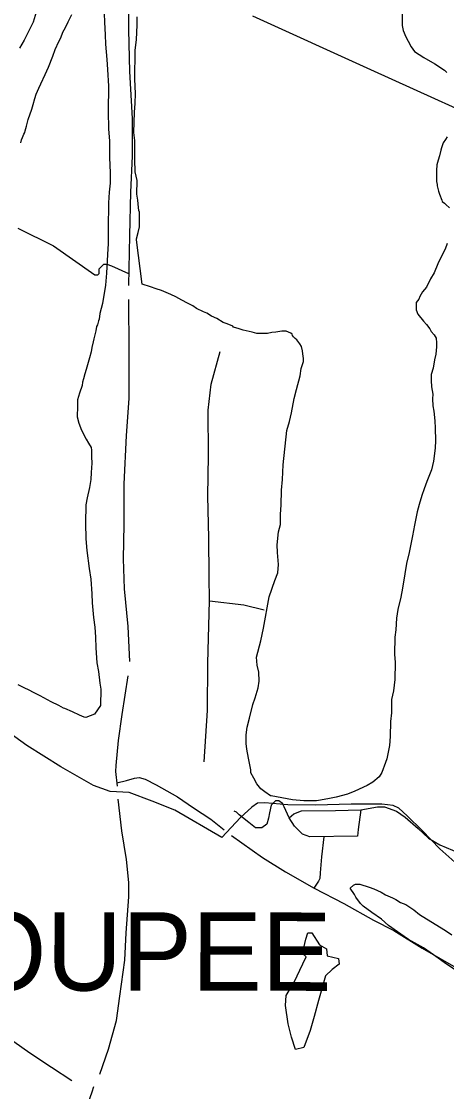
# Model space of a CAD drawing. Extents: x 3263578 to 3301413, y 764927 to 798602.
# Drawn here: x 3272360 to 3273446, y 781990 to 784722 of the extents above; entities that cross this region are included whole.
import ezdxf

# ---------------------------------------------------------------- set-up
doc = ezdxf.new("R2010")
doc.units = 0
for name, color, linetype in [('V-ROAD-CNTR', 7, 'Continuous'), ('V-SITE-VEGE', 7, 'Continuous'), ('V-TOPO-GNAM-IDEN', 7, 'Continuous'), ('V-TOPO-SHOR', 7, 'Continuous')]:
    doc.layers.add(name, color=color, linetype=linetype)

msp = doc.modelspace()

# ---------------------------------------------------------------- linework, layer by layer
at = {"layer": 'V-ROAD-CNTR'}
for points in [[(3272871.3, 782638.4), (3272751.2, 782707.9), (3272693.7, 782731), (3272634.6, 782753.7), (3272586.4, 782755.6), (3272544.2, 782771.2), (3272460.4, 782818.6), (3272374.1, 782873), (3272302.5, 782924.3)], [(3273887.3, 782394.1), (3273845.6, 782422.1), (3273790.5, 782448.5), (3273704.1, 782475), (3273634.8, 782502), (3273573.5, 782523.4), (3273524.5, 782537.4), (3273481.9, 782562.3), (3273428.5, 782609.9), (3273383.6, 782656.6), (3273344.9, 782694.2), (3273323.2, 782713.3), (3273309.1, 782720.4), (3273280.1, 782723.2), (3273202.1, 782723.7), (3273111.2, 782721.1), (3273040.2, 782722.2), (3272981.6, 782727.4), (3272962.7, 782725.9), (3272948.4, 782716.1), (3272919.2, 782689.5), (3272871.3, 782638.4)]]:
    msp.add_lwpolyline(points, dxfattribs=at)
at = {"layer": 'V-SITE-VEGE'}
for points in [[(3272566.9, 784897.4), (3272566.8, 784890.8), (3272565.5, 784879.7), (3272566.3, 784859.7), (3272566.1, 784844.1), (3272568.2, 784837.4), (3272567.5, 784796.3), (3272568.1, 784766.3), (3272571.1, 784742.9), (3272571.9, 784720.7), (3272573.6, 784688.4), (3272574.3, 784664)], [(3272397.8, 784745.7), (3272389.6, 784720.3), (3272381.6, 784703.7), (3272366.7, 784674), (3272355.2, 784654.1)], [(3272358, 784411.9), (3272360.4, 784419.6), (3272362.7, 784426.2), (3272366.1, 784434), (3272368.4, 784438.4), (3272369.6, 784442.8), (3272373.1, 784455), (3272376.7, 784471.6), (3272386.1, 784498.1), (3272389.6, 784510.3), (3272394.3, 784525.7), (3272397.8, 784536.8), (3272404.7, 784552.2), (3272409.3, 784563.3), (3272420.8, 784586.4), (3272428.9, 784605.2), (3272440.5, 784633.9), (3272446.3, 784650.5), (3272455.5, 784671.4), (3272460.1, 784680.2), (3272465.9, 784694.6), (3272472.7, 784706.7), (3272479.6, 784721), (3272488.8, 784739.8)], [(3272945.7, 782811.3), (3272942.6, 782828), (3272939.5, 782841.4), (3272935.4, 782863.7), (3272933.4, 782878.1), (3272933.8, 782900.3), (3272936.3, 782920.3), (3272942.2, 782943.5), (3272950.6, 782977.9), (3272956.4, 782995.5), (3272964.6, 783021), (3272967.1, 783037.6), (3272966.3, 783060.9), (3272962.2, 783078.8), (3272960.3, 783098.8), (3272971, 783140.9), (3272978.1, 783173), (3272992.8, 783252.8), (3273006.8, 783294.7), (3273014.9, 783314.6), (3273016.3, 783335.7), (3273013.5, 783365.8), (3273012.7, 783385.8), (3273016.5, 783419), (3273021.3, 783437.9), (3273021.7, 783464.5), (3273023.2, 783486.7), (3273023.8, 783525.6), (3273026.5, 783552.2), (3273028.2, 783590), (3273037.4, 783677.6), (3273044.4, 783700.8), (3273049.2, 783723), (3273056.4, 783759.5), (3273062.4, 783782.8), (3273071.8, 783817.1), (3273074.3, 783835.9), (3273080.2, 783853.6), (3273080.3, 783861.4), (3273078.3, 783873.6), (3273077.3, 783881.4), (3273075.2, 783892.6), (3273070.9, 783899.3), (3273063.3, 783909.4), (3273058.9, 783912.8), (3273054.5, 783917.3), (3273052.4, 783920.7), (3273051.3, 783924.1), (3273048, 783926.3), (3273035.9, 783931), (3273024.8, 783931.2), (3273009.2, 783929.2), (3272999.2, 783928.2), (3272988, 783925.1), (3272961.3, 783925.5), (3272949.2, 783929), (3272925.9, 783933.8), (3272916, 783937.3), (3272901.6, 783942), (3272899.4, 783944.3), (3272885.1, 783950.1), (3272875.1, 783953.6), (3272858.6, 783963.8), (3272845.4, 783969.6), (3272833.3, 783977.6), (3272824.4, 783981), (3272806.8, 783989.1), (3272798, 783995.9), (3272783.7, 784002.8), (3272769.4, 784010.8), (3272753.9, 784018.8), (3272741.8, 784024.6), (3272717.5, 784035), (3272704.3, 784039.6), (3272689.9, 784044.3), (3272667.8, 784051.3), (3272654.1, 784164.9), (3272654.1, 784167.1), (3272657.7, 784183.7), (3272661.3, 784198.1), (3272661.8, 784234.8), (3272659.7, 784239.2), (3272658.7, 784247), (3272656.8, 784266), (3272654.8, 784281.5), (3272655.4, 784316), (3272650.2, 784338.3), (3272649.6, 784369.4), (3272649.9, 784390.5), (3272649.2, 784418.3), (3272647.3, 784438.3), (3272648.2, 784490.5), (3272650.7, 784512.7), (3272651.2, 784538.3), (3272649.5, 784575), (3272650.7, 784648.3), (3272653.4, 784676), (3272655.1, 784712.7), (3272655.4, 784733.8)], [(3273332.3, 784745.1), (3273331.7, 784711.8), (3273334.9, 784699.5), (3273341.3, 784682.8), (3273347.8, 784671.5), (3273355.3, 784657), (3273364, 784645.7), (3273387.1, 784629.8), (3273415.7, 784613.8), (3273439.9, 784597.8), (3273446.5, 784592.2)], [(3272574.3, 784664), (3272578.1, 784625), (3272579.9, 784599.4), (3272582.6, 784557.2), (3272581.5, 784492.7), (3272581.9, 784447.2), (3272584.8, 784417.1), (3272585.2, 784374.9), (3272586.8, 784336), (3272586.4, 784309.3), (3272583.8, 784286), (3272582.2, 784259.4), (3272581.2, 784192.7), (3272581.7, 784154.9), (3272580.1, 784127.2), (3272577.1, 784079.5), (3272574.4, 784048.4), (3272567, 784001.8), (3272559.9, 783976.4), (3272558.6, 783962), (3272556.3, 783957.6), (3272553.9, 783947.6), (3272551.6, 783943.2), (3272550.3, 783932.1), (3272544.4, 783912.2), (3272543.2, 783904.4), (3272539.6, 783890), (3272538.3, 783879), (3272533.7, 783863.5), (3272530.1, 783851.3), (3272525.4, 783833.6), (3272521.9, 783822.6), (3272518.3, 783809.3), (3272516, 783801.5), (3272514.7, 783792.7), (3272507.8, 783772.8), (3272503, 783756.2), (3272502.8, 783739.5), (3272502.3, 783712.9), (3272506.5, 783696.1), (3272512.9, 783678.2), (3272524.8, 783655.8), (3272531.3, 783645.7), (3272537.8, 783634.5), (3272538.8, 783627.8), (3272538.5, 783610.1), (3272539.3, 783594.5), (3272537.8, 783570.1), (3272537.5, 783552.3), (3272533.9, 783532.3), (3272527.9, 783505.8), (3272524.3, 783488.1), (3272523.5, 783441.4), (3272524, 783401.4), (3272526.9, 783371.3), (3272532.8, 783325.7), (3272536.8, 783297.8), (3272539.5, 783261.1), (3272540.3, 783237.8), (3272544.1, 783200), (3272547.1, 783175.5), (3272548.9, 783149.9), (3272549.5, 783123.2), (3272552.3, 783084.3), (3272556.3, 783062), (3272560.3, 783033), (3272562.3, 783017.4), (3272561.6, 782975.2), (3272546.8, 782953.2), (3272524.5, 782944.7), (3272520, 782945.9), (3272507.9, 782950.5), (3272490.3, 782959.7), (3272470.4, 782967.8), (3272467.1, 782969), (3272455, 782975.8), (3272436.2, 782985), (3272407.6, 782999.9), (3272392.1, 783007.9), (3272377.8, 783015.9), (3272369, 783019.4), (3272351.4, 783028.6)], [(3273447.2, 784427.7), (3273442.6, 784421.1), (3273436.9, 784412.3), (3273432.3, 784399.1), (3273431.1, 784393.5), (3273427.5, 784379.1), (3273424, 784368.1), (3273420.5, 784355.9), (3273420.2, 784341.5), (3273419.8, 784313.7), (3273421.9, 784305.9), (3273421.8, 784302.6), (3273422.8, 784295.9), (3273425, 784289.2), (3273427.1, 784281.4), (3273433.5, 784265.7), (3273434.5, 784262.4), (3273440, 784257.8), (3273443.3, 784254.4), (3273453.2, 784246.5)], [(3273447.3, 784155.5), (3273441.5, 784141.1), (3273431.1, 784119.1), (3273423.1, 784103.6), (3273413.8, 784080.5), (3273404.7, 784065.1), (3273394.4, 784044.1), (3273384.2, 784032), (3273377.3, 784019.9), (3273375, 784013.3), (3273368.2, 784004.5), (3273367.9, 783985.6), (3273372.1, 783974.5), (3273386.3, 783956.5), (3273393.9, 783948.6), (3273402.6, 783937.3), (3273405.9, 783930.6), (3273413.5, 783921.6), (3273418.9, 783913.7), (3273419.9, 783901.5), (3273419.7, 783891.5), (3273418.3, 783872.6), (3273414.7, 783858.2), (3273411, 783837.2), (3273406.3, 783820.6), (3273406.1, 783805), (3273406.9, 783789.5), (3273410, 783770.5), (3273409.8, 783758.3), (3273410.6, 783740.5), (3273412.6, 783727.1), (3273415.5, 783702.6), (3273416.4, 783683.7), (3273417, 783652.6), (3273416.6, 783632.6), (3273411.7, 783599.4), (3273406.9, 783577.2), (3273395.3, 783547.4), (3273388.3, 783528.6), (3273382.5, 783512.1), (3273375.4, 783488.8), (3273370.7, 783470), (3273363.5, 783435.7), (3273358.6, 783409.1), (3273350.1, 783365.9), (3273343, 783338.2), (3273339.3, 783311.6), (3273333.1, 783275.1), (3273328.3, 783251.8), (3273321.1, 783220.8), (3273317.5, 783198.6), (3273315.9, 783168.7), (3273313.3, 783149.8), (3273312.6, 783106.5), (3273314.5, 783085.4), (3273313.8, 783042), (3273310, 783013.2), (3273305.2, 782991.1), (3273304.7, 782956.6), (3273302.1, 782934.4), (3273301.5, 782896.7), (3273300, 782873.4), (3273292.8, 782839), (3273289.3, 782830.2), (3273280, 782804.8), (3273273.2, 782793.8), (3273257.4, 782779.6), (3273242.8, 782770.9), (3273211.5, 782757), (3273192.5, 782749.5), (3273163.4, 782741.1), (3273146.7, 782738), (3273123.3, 782734), (3273113.3, 782731.9), (3273081.1, 782732.4), (3273052.2, 782735.1), (3273024.5, 782740), (3272997.9, 782744.9), (3272995.7, 782744.9), (3272981.4, 782755.1), (3272971.6, 782763.1), (3272960.6, 782775.5), (3272953.1, 782790), (3272945.5, 782803.5), (3272945.7, 782811.3)], [(3273467.5, 782300.6), (3273445.5, 782315.4), (3273412.5, 782339.3), (3273386.2, 782356.4), (3273348.7, 782378.1), (3273328.9, 782391.8), (3273297.1, 782413.4), (3273279.6, 782430.3), (3273254.3, 782447.4), (3273232.3, 782463.3), (3273225.8, 782470.1), (3273213.8, 782485.8), (3273210.6, 782492.6), (3273199.7, 782509.4), (3273207.6, 782517.1), (3273213.2, 782519.2), (3273224.3, 782519), (3273247.5, 782512), (3273259.7, 782507.3), (3273278.4, 782499.2), (3273289.4, 782492.4), (3273307.1, 782484.3), (3273315.9, 782479.8), (3273328, 782472.9), (3273341.3, 782467.1), (3273362.2, 782453.5), (3273376.4, 782442.1), (3273416, 782417), (3273442.4, 782401.1), (3273458.9, 782389.7)]]:
    msp.add_lwpolyline(points, dxfattribs=at)
at = {"layer": 'V-TOPO-SHOR'}
for points in [[(3272634.4, 784048.1), (3272636.5, 784175.5), (3272638.9, 784286.4), (3272643.1, 784378.6), (3272643.6, 784474.6), (3272637, 784594.1), (3272634.5, 784700.4), (3272633.2, 784804.9)], [(3272950.2, 784736.4), (3273251.6, 784599.4), (3273623.3, 784431.1), (3274018.6, 784231.5), (3274269, 784129.7), (3274476.4, 784035.8), (3274574.3, 783992.7), (3274683.8, 783937.9), (3274906.9, 783832.3), (3275004.7, 783781.4), (3275306.1, 783640.5), (3275501.7, 783542.6)], [(3272350.4, 784194.2), (3272441.4, 784149.5), (3272547.1, 784075.1), (3272554.9, 784075.1), (3272558.8, 784079), (3272558.8, 784090.7), (3272570.6, 784102.5), (3272578.4, 784102.5), (3272590.1, 784098.6), (3272633.2, 784079)], [(3272632.9, 784012.5), (3272634.1, 783879.3), (3272634.5, 783759.6), (3272627.4, 783664.8), (3272621.8, 783540.4), (3272621, 783437.7), (3272619.4, 783350.3), (3272622.1, 783273.4), (3272631.2, 783177.1), (3272636, 783087.6)], [(3272840, 783243.2), (3272838.9, 783306.2), (3272838.4, 783403.9), (3272835.7, 783510.1), (3272837.6, 783613.8), (3272836.9, 783729.3), (3272844.1, 783796.3), (3272867.6, 783879.5)], [(3272826.7, 782831.9), (3272834.7, 782963.2), (3272835.6, 783084), (3272840, 783243.2), (3272927.9, 783232.9), (3272979.9, 783220)], [(3272631.8, 783051.1), (3272616.5, 782952.6), (3272606.5, 782886.4), (3272600.7, 782822.2), (3272600.3, 782806.8), (3272604.5, 782769.9)], [(3272603.6, 782778.2), (3272628.1, 782784), (3272648.5, 782789.7), (3272660.9, 782791.3), (3272675.8, 782787.3), (3272703.9, 782773.2), (3272758, 782742.1), (3272799.1, 782714.6), (3272843.4, 782685.4), (3272877.5, 782658)], [(3272627.6, 782395.5), (3272634.4, 782487), (3272634.2, 782524), (3272628.4, 782582.2), (3272616.5, 782655.5), (3272606.9, 782736.3)], [(3273043.9, 782688.5), (3273030.8, 782716.6), (3273026.4, 782725.4), (3273017.6, 782732), (3273008.8, 782732), (3272997.7, 782721), (3272993.3, 782701.1), (3272991.1, 782687.9), (3272986.7, 782672.4), (3272973.5, 782663.6), (3272958, 782663.6), (3272940.3, 782676.8), (3272916.1, 782696.7), (3272909.5, 782703.3), (3272902.8, 782705.5)], [(3273162.3, 782707.7), (3273226.5, 782709.3), (3273219.6, 782658.6), (3273218.1, 782641.5), (3273096.2, 782640.5), (3273077.6, 782646.8), (3273056.8, 782667.2), (3273043.9, 782688.5), (3273055.3, 782698.6), (3273074.8, 782706.6), (3273162.3, 782707.7)], [(3273226.5, 782709.3), (3273269.2, 782716.5), (3273286.8, 782716.5), (3273317.7, 782705.5), (3273339.8, 782690), (3273372.9, 782661.4), (3273399.4, 782637.1), (3273428.1, 782619.4), (3273476.6, 782599.6), (3273496.5, 782581.9), (3273509.7, 782570.9), (3273514.1, 782566.4)], [(3272895.9, 782643.5), (3272975.8, 782587.7), (3273034.5, 782551.1), (3273107.5, 782509.5), (3273183.3, 782470.1), (3273259.2, 782427.1), (3273310.6, 782401.3)], [(3273131.9, 782639.8), (3273126.2, 782589.3), (3273122.9, 782548.6), (3273122.1, 782533.4), (3273118.8, 782527.4), (3273106.3, 782508.8)], [(3273310.6, 782401.3), (3273383.2, 782356.1), (3273481, 782299.8), (3273551.9, 782255.1), (3273633.8, 782204.6), (3273741.1, 782139.1), (3273769, 782119.4), (3273847, 782081.6), (3273900.5, 782047.1), (3273933.1, 782027.7), (3273974.1, 782003.2), (3274031.4, 781965.9)], [(3271994.7, 782383.4), (3272013.4, 782365.7), (3272101.5, 782296.2), (3272184.7, 782229.6), (3272246.2, 782183.5), (3272320.5, 782131.8), (3272381.6, 782088.6), (3272436.6, 782052.3), (3272488.6, 782018.2)], [(3272560.5, 782034.6), (3272582.2, 782097.8), (3272602.4, 782171.6), (3272611.3, 782233.1), (3272624.2, 782325.7), (3272627.6, 782395.5)], [(3273086.5, 782378.9), (3273091.4, 782395.5), (3273101.1, 782394.9), (3273120.9, 782364.4), (3273138.5, 782354.1), (3273140.5, 782336.5), (3273169.4, 782329.9), (3273171.2, 782314.7), (3273153.4, 782301.8), (3273136.2, 782285.5), (3273118.3, 782222), (3273107.3, 782181.8), (3273097.6, 782145.6), (3273081.4, 782102.7), (3273059.6, 782097.4), (3273049.7, 782129.1), (3273041.2, 782163), (3273034.4, 782209.8), (3273036, 782235.4), (3273056.7, 782268.9), (3273078.5, 782315.9), (3273087, 782333.9), (3273077.6, 782342.6), (3273086.5, 782378.9)], [(3272368.2, 781408.2), (3272400.2, 781490.9), (3272428.8, 781575.5), (3272452.6, 781673.5), (3272476.8, 781773.4), (3272496.2, 781865), (3272540.8, 781989.4), (3272544.9, 782002.3)]]:
    msp.add_lwpolyline(points, dxfattribs=at)

# ---------------------------------------------------------------- texts
at = {"layer": 'V-TOPO-GNAM-IDEN'}
msp.add_text('COUPEE', height=200, rotation=359.9292, dxfattribs=at).set_placement((3272022.4, 782248.3))

doc.saveas('drawing.dxf')
